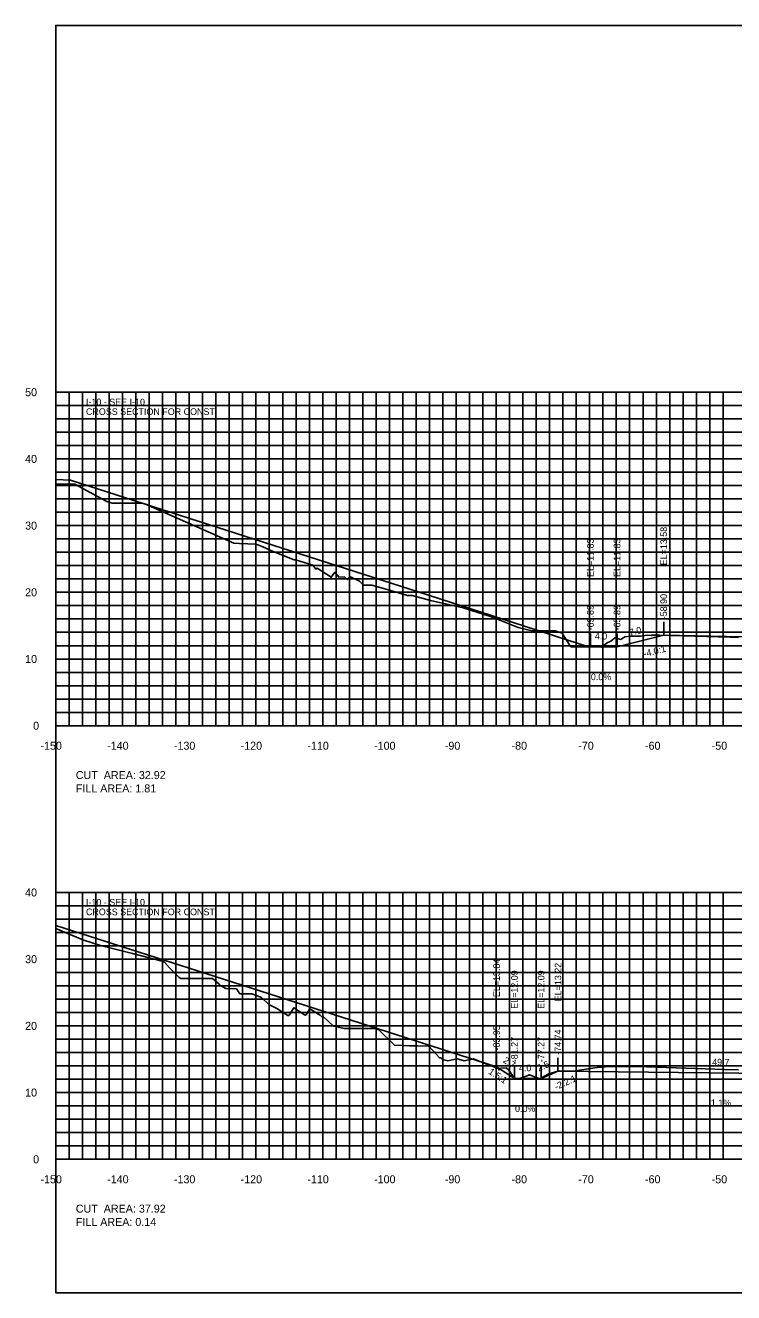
# Model space of a CAD drawing. Extents: x 1797652 to 1804145, y 245981 to 250269.
# Drawn here: x 1802136.4 to 1802242.6, y 250079.4 to 250269.4 of the extents above; entities that cross this region are included whole.
import ezdxf

# ---------------------------------------------------------------- set-up
doc = ezdxf.new("R2010")
doc.units = 0
for name, color, linetype in [('10', 7, 'Continuous'), ('3', 7, 'Continuous'), ('31', 7, 'Continuous'), ('4', 7, 'Continuous'), ('60', 7, 'Continuous'), ('ANNO-TXT', 7, 'Continuous'), ('CL-CNST', 7, 'Continuous'), ('Level 62', 7, 'Continuous'), ('M-ROADS', 7, 'Continuous')]:
    doc.layers.add(name, color=color, linetype=linetype)

msp = doc.modelspace()

# ---------------------------------------------------------------- linework, layer by layer
for p, q in [((1802232.1, 250178.01), (1802232.1, 250180.01)), ((1802221.11, 250176.26), (1802221.11, 250178.26)), ((1802225.11, 250176.26), (1802225.11, 250178.26)), ((1802207.05, 250113.27), (1802207.05, 250115.27)), ((1802216.26, 250112.65), (1802216.26, 250114.65)), ((1802209.73, 250111.52), (1802209.73, 250113.52)), ((1802213.73, 250111.52), (1802213.73, 250113.52))]:
    msp.add_line(p, q)
msp.add_lwpolyline([(1802141, 250079.43), (1802441, 250079.43), (1802441, 250269.43), (1802141, 250269.43)], close=True)
at = {"layer": '60'}
for p, q in [((1802140.94, 250214.43), (1802141, 250214.43)), ((1802141, 250164.43), (1802141, 250214.43)), ((1802140.94, 250204.43), (1802141, 250204.43)), ((1802140.94, 250194.43), (1802141, 250194.43)), ((1802140.94, 250184.43), (1802141, 250184.43)), ((1802140.94, 250174.43), (1802141, 250174.43)), ((1802140.94, 250164.43), (1802141, 250164.43)), ((1802141, 250164.43), (1802441, 250164.43)), ((1802141, 250164.37), (1802141, 250164.43)), ((1802151, 250164.37), (1802151, 250164.43)), ((1802161, 250164.37), (1802161, 250164.43)), ((1802171, 250164.37), (1802171, 250164.43)), ((1802181, 250164.37), (1802181, 250164.43)), ((1802191, 250164.37), (1802191, 250164.43)), ((1802201, 250164.37), (1802201, 250164.43)), ((1802211, 250164.37), (1802211, 250164.43)), ((1802221, 250164.37), (1802221, 250164.43)), ((1802231, 250164.37), (1802231, 250164.43)), ((1802241, 250164.37), (1802241, 250164.43)), ((1802140.94, 250139.43), (1802141, 250139.43)), ((1802141, 250099.43), (1802141, 250139.43)), ((1802140.94, 250129.43), (1802141, 250129.43)), ((1802140.94, 250119.43), (1802141, 250119.43)), ((1802140.94, 250109.43), (1802141, 250109.43)), ((1802140.94, 250099.43), (1802141, 250099.43)), ((1802141, 250099.43), (1802441, 250099.43)), ((1802141, 250099.37), (1802141, 250099.43)), ((1802151, 250099.37), (1802151, 250099.43)), ((1802161, 250099.37), (1802161, 250099.43)), ((1802171, 250099.37), (1802171, 250099.43)), ((1802181, 250099.37), (1802181, 250099.43)), ((1802191, 250099.37), (1802191, 250099.43)), ((1802201, 250099.37), (1802201, 250099.43)), ((1802211, 250099.37), (1802211, 250099.43)), ((1802221, 250099.37), (1802221, 250099.43)), ((1802231, 250099.37), (1802231, 250099.43)), ((1802241, 250099.37), (1802241, 250099.43))]:
    msp.add_line(p, q, dxfattribs=at)
at = {"layer": 'CL-CNST'}
msp.add_line((1802220.79, 250176.26), (1802224.11, 250176.26), dxfattribs=at)
for points in [[(1802141, 250201.34), (1802143.21, 250201.25), (1802196.84, 250183.99), (1802220.81, 250176.25)], [(1802221.11, 250176.26), (1802225.11, 250176.26), (1802232.1, 250178.01), (1802265.01, 250177.32), (1802269.01, 250177.16), (1802269.34, 250177.16), (1802269.51, 250176.66), (1802271.51, 250176.82), (1802275, 250176.89), (1802291, 250177.24), (1802299, 250177.3), (1802301, 250177.31), (1802301.5, 250177.4)], [(1802141, 250134.5), (1802163.5, 250127.27), (1802200.18, 250115.48), (1802207.05, 250113.27)], [(1802207.05, 250113.27), (1802209.73, 250111.52), (1802213.73, 250111.52), (1802216.26, 250112.65), (1802265.99, 250112.11), (1802269.99, 250111.95), (1802270.32, 250111.95), (1802270.49, 250111.45), (1802272.49, 250111.61), (1802275, 250111.66), (1802291, 250112.01), (1802299, 250112.19), (1802301.49, 250112.69)]]:
    msp.add_lwpolyline(points, dxfattribs=at)
at = {"layer": 'Level 62'}
for p, q in [((1802141, 250214.43), (1802441, 250214.43)), ((1802141, 250164.43), (1802141, 250214.43)), ((1802143, 250164.43), (1802143, 250214.43)), ((1802145, 250164.43), (1802145, 250214.43)), ((1802147, 250164.43), (1802147, 250214.43)), ((1802149, 250164.43), (1802149, 250214.43)), ((1802151, 250164.43), (1802151, 250214.43)), ((1802153, 250164.43), (1802153, 250214.43)), ((1802155, 250164.43), (1802155, 250214.43)), ((1802157, 250164.43), (1802157, 250214.43)), ((1802159, 250164.43), (1802159, 250214.43)), ((1802161, 250164.43), (1802161, 250214.43)), ((1802163, 250164.43), (1802163, 250214.43)), ((1802165, 250164.43), (1802165, 250214.43)), ((1802167, 250164.43), (1802167, 250214.43)), ((1802169, 250164.43), (1802169, 250214.43)), ((1802171, 250164.43), (1802171, 250214.43)), ((1802173, 250164.43), (1802173, 250214.43)), ((1802175, 250164.43), (1802175, 250214.43)), ((1802177, 250164.43), (1802177, 250214.43)), ((1802179, 250164.43), (1802179, 250214.43)), ((1802181, 250164.43), (1802181, 250214.43)), ((1802183, 250164.43), (1802183, 250214.43)), ((1802185, 250164.43), (1802185, 250214.43)), ((1802187, 250164.43), (1802187, 250214.43)), ((1802189, 250164.43), (1802189, 250214.43)), ((1802191, 250164.43), (1802191, 250214.43)), ((1802193, 250164.43), (1802193, 250214.43)), ((1802195, 250164.43), (1802195, 250214.43)), ((1802197, 250164.43), (1802197, 250214.43)), ((1802199, 250164.43), (1802199, 250214.43)), ((1802201, 250164.43), (1802201, 250214.43)), ((1802203, 250164.43), (1802203, 250214.43)), ((1802205, 250164.43), (1802205, 250214.43)), ((1802207, 250164.43), (1802207, 250214.43)), ((1802209, 250164.43), (1802209, 250214.43)), ((1802211, 250164.43), (1802211, 250214.43)), ((1802213, 250164.43), (1802213, 250214.43)), ((1802215, 250164.43), (1802215, 250214.43)), ((1802217, 250164.43), (1802217, 250214.43)), ((1802219, 250164.43), (1802219, 250214.43)), ((1802221, 250164.43), (1802221, 250214.43)), ((1802223, 250164.43), (1802223, 250214.43)), ((1802225, 250164.43), (1802225, 250214.43)), ((1802227, 250164.43), (1802227, 250214.43)), ((1802229, 250164.43), (1802229, 250214.43)), ((1802231, 250164.43), (1802231, 250214.43)), ((1802233, 250164.43), (1802233, 250214.43)), ((1802235, 250164.43), (1802235, 250214.43)), ((1802237, 250164.43), (1802237, 250214.43)), ((1802239, 250164.43), (1802239, 250214.43)), ((1802241, 250164.43), (1802241, 250214.43)), ((1802141, 250212.43), (1802441, 250212.43)), ((1802141, 250210.43), (1802441, 250210.43)), ((1802141, 250208.43), (1802441, 250208.43)), ((1802141, 250206.43), (1802441, 250206.43)), ((1802141, 250204.43), (1802441, 250204.43)), ((1802141, 250202.43), (1802441, 250202.43)), ((1802141, 250200.43), (1802441, 250200.43)), ((1802141, 250198.43), (1802441, 250198.43)), ((1802141, 250196.43), (1802441, 250196.43)), ((1802141, 250194.43), (1802441, 250194.43)), ((1802141, 250192.43), (1802441, 250192.43)), ((1802141, 250190.43), (1802441, 250190.43)), ((1802141, 250188.43), (1802441, 250188.43)), ((1802141, 250186.43), (1802441, 250186.43)), ((1802141, 250184.43), (1802441, 250184.43)), ((1802141, 250182.43), (1802441, 250182.43)), ((1802141, 250180.43), (1802441, 250180.43)), ((1802141, 250178.43), (1802441, 250178.43)), ((1802141, 250176.43), (1802441, 250176.43)), ((1802141, 250174.43), (1802441, 250174.43)), ((1802141, 250172.43), (1802441, 250172.43)), ((1802141, 250170.43), (1802441, 250170.43)), ((1802141, 250168.43), (1802441, 250168.43)), ((1802141, 250166.43), (1802441, 250166.43)), ((1802141, 250164.43), (1802441, 250164.43)), ((1802141, 250139.43), (1802441, 250139.43)), ((1802141, 250099.43), (1802141, 250139.43)), ((1802143, 250099.43), (1802143, 250139.43)), ((1802145, 250099.43), (1802145, 250139.43)), ((1802147, 250099.43), (1802147, 250139.43)), ((1802149, 250099.43), (1802149, 250139.43)), ((1802151, 250099.43), (1802151, 250139.43)), ((1802153, 250099.43), (1802153, 250139.43)), ((1802155, 250099.43), (1802155, 250139.43)), ((1802157, 250099.43), (1802157, 250139.43)), ((1802159, 250099.43), (1802159, 250139.43)), ((1802161, 250099.43), (1802161, 250139.43)), ((1802163, 250099.43), (1802163, 250139.43)), ((1802165, 250099.43), (1802165, 250139.43)), ((1802167, 250099.43), (1802167, 250139.43)), ((1802169, 250099.43), (1802169, 250139.43)), ((1802171, 250099.43), (1802171, 250139.43)), ((1802173, 250099.43), (1802173, 250139.43)), ((1802175, 250099.43), (1802175, 250139.43)), ((1802177, 250099.43), (1802177, 250139.43)), ((1802179, 250099.43), (1802179, 250139.43)), ((1802181, 250099.43), (1802181, 250139.43)), ((1802183, 250099.43), (1802183, 250139.43)), ((1802185, 250099.43), (1802185, 250139.43)), ((1802187, 250099.43), (1802187, 250139.43)), ((1802189, 250099.43), (1802189, 250139.43)), ((1802191, 250099.43), (1802191, 250139.43)), ((1802193, 250099.43), (1802193, 250139.43)), ((1802195, 250099.43), (1802195, 250139.43)), ((1802197, 250099.43), (1802197, 250139.43)), ((1802199, 250099.43), (1802199, 250139.43)), ((1802201, 250099.43), (1802201, 250139.43)), ((1802203, 250099.43), (1802203, 250139.43)), ((1802205, 250099.43), (1802205, 250139.43)), ((1802207, 250099.43), (1802207, 250139.43)), ((1802209, 250099.43), (1802209, 250139.43)), ((1802211, 250099.43), (1802211, 250139.43)), ((1802213, 250099.43), (1802213, 250139.43)), ((1802215, 250099.43), (1802215, 250139.43)), ((1802217, 250099.43), (1802217, 250139.43)), ((1802219, 250099.43), (1802219, 250139.43)), ((1802221, 250099.43), (1802221, 250139.43)), ((1802223, 250099.43), (1802223, 250139.43)), ((1802225, 250099.43), (1802225, 250139.43)), ((1802227, 250099.43), (1802227, 250139.43)), ((1802229, 250099.43), (1802229, 250139.43)), ((1802231, 250099.43), (1802231, 250139.43)), ((1802233, 250099.43), (1802233, 250139.43)), ((1802235, 250099.43), (1802235, 250139.43)), ((1802237, 250099.43), (1802237, 250139.43)), ((1802239, 250099.43), (1802239, 250139.43)), ((1802241, 250099.43), (1802241, 250139.43)), ((1802141, 250137.43), (1802441, 250137.43)), ((1802141, 250135.43), (1802441, 250135.43)), ((1802141, 250133.43), (1802441, 250133.43)), ((1802141, 250131.43), (1802441, 250131.43)), ((1802141, 250129.43), (1802441, 250129.43)), ((1802141, 250127.43), (1802441, 250127.43)), ((1802141, 250125.43), (1802441, 250125.43)), ((1802141, 250123.43), (1802441, 250123.43)), ((1802141, 250121.43), (1802441, 250121.43)), ((1802141, 250119.43), (1802441, 250119.43)), ((1802141, 250117.43), (1802441, 250117.43)), ((1802141, 250115.43), (1802441, 250115.43)), ((1802141, 250113.43), (1802441, 250113.43)), ((1802141, 250111.43), (1802441, 250111.43)), ((1802141, 250109.43), (1802441, 250109.43)), ((1802141, 250107.43), (1802441, 250107.43)), ((1802141, 250105.43), (1802441, 250105.43)), ((1802141, 250103.43), (1802441, 250103.43)), ((1802141, 250101.43), (1802441, 250101.43)), ((1802141, 250099.43), (1802441, 250099.43))]:
    msp.add_line(p, q, dxfattribs=at)
at = {"layer": 'M-ROADS'}
for points in [[(1802141, 250200.66), (1802141.59, 250200.66), (1802143.86, 250200.66), (1802148.66, 250198.03), (1802149.47, 250197.8), (1802151.76, 250197.8), (1802153.92, 250197.8), (1802154.62, 250197.58), (1802154.89, 250197.47), (1802167.68, 250191.79), (1802168.54, 250191.74), (1802171.03, 250191.67), (1802171.8, 250191.34), (1802172.01, 250191.26), (1802173.31, 250190.64), (1802176.74, 250189.28), (1802176.94, 250189.28), (1802179.51, 250188.52), (1802179.98, 250187.9), (1802180.15, 250188.05), (1802182.28, 250186.68), (1802182.84, 250187.43), (1802183.41, 250186.68), (1802184.25, 250186.75), (1802184.67, 250186.33), (1802185.16, 250186.74), (1802186.51, 250186.08), (1802187.09, 250185.5), (1802188.34, 250185.5), (1802190.33, 250184.93), (1802193.71, 250183.96), (1802194.07, 250183.96), (1802194.42, 250183.96), (1802197.15, 250183.18), (1802202.04, 250182.09), (1802206.28, 250180.73), (1802210.27, 250179.16), (1802211.3, 250178.91), (1802212.37, 250178.64), (1802214.16, 250178.64), (1802215.85, 250178.64), (1802216.88, 250178.32), (1802218.11, 250176.31), (1802218.3, 250176.26), (1802220.49, 250176.26), (1802220.64, 250176.25), (1802220.8, 250176.25), (1802222, 250176.28), (1802222.03, 250176.26), (1802222.8, 250176.23), (1802223.63, 250176.86), (1802224.18, 250177.11), (1802224.8, 250177.61), (1802225.66, 250177.37), (1802226.27, 250177.76), (1802227.13, 250177.85), (1802228.64, 250177.85), (1802229.31, 250177.96), (1802229.72, 250178.02), (1802230.24, 250177.96), (1802230.34, 250178.02), (1802231.46, 250178.03), (1802242, 250177.69), (1802243.29, 250177.69)], [(1802141, 250134.05), (1802145.04, 250132.31), (1802147.87, 250131.42), (1802147.88, 250131.42), (1802147.88, 250131.42), (1802152.48, 250130.26), (1802156.94, 250129.14), (1802157.16, 250129.04), (1802157.31, 250128.99), (1802158.02, 250128.13), (1802159.49, 250126.67), (1802159.75, 250126.53), (1802161.99, 250126.54), (1802163.95, 250126.54), (1802164.49, 250126.54), (1802165.42, 250125.74), (1802165.56, 250125.51), (1802166.46, 250125.05), (1802168.06, 250125), (1802168.59, 250124.21), (1802170.4, 250124.21), (1802170.93, 250124.01), (1802171.83, 250123.67), (1802172.94, 250122.64), (1802174.11, 250122.02), (1802175.79, 250120.99), (1802175.95, 250120.99), (1802175.98, 250121.04), (1802176.69, 250122.14), (1802178.26, 250121.08), (1802178.46, 250121.01), (1802179.08, 250121.98), (1802180.64, 250121.03), (1802180.85, 250120.8), (1802181.11, 250120.8), (1802182.59, 250119.45), (1802182.65, 250119.4), (1802182.67, 250119.38), (1802182.91, 250119.33), (1802184.22, 250119.03), (1802184.29, 250119.03), (1802186.68, 250119.04), (1802186.77, 250119.02), (1802189.05, 250119.02), (1802189.25, 250118.91), (1802189.35, 250118.9), (1802191.74, 250116.53), (1802193.99, 250116.43), (1802194.58, 250116.42), (1802194.68, 250116.43), (1802195.25, 250116.42), (1802196.81, 250116.4), (1802196.91, 250116.41), (1802198.48, 250114.64), (1802198.63, 250114.64), (1802199.13, 250114.34), (1802199.77, 250114.19), (1802200.63, 250114.39), (1802201.08, 250114.5), (1802201.21, 250114.5), (1802201.35, 250114.42), (1802202.19, 250114.17), (1802203.58, 250114.5), (1802203.59, 250114.5), (1802204.71, 250114.05), (1802207.12, 250113.08), (1802207.32, 250113.08), (1802207.41, 250112.8), (1802207.68, 250113.09), (1802208.47, 250113.12), (1802208.87, 250112.78), (1802209.73, 250111.52), (1802210.37, 250111.48), (1802211.89, 250112.04), (1802211.93, 250112.12), (1802211.98, 250112.07), (1802211.99, 250112.05), (1802212.14, 250112.05), (1802213.51, 250111.51), (1802214.88, 250112.24), (1802216.26, 250112.65), (1802218.81, 250112.71), (1802222.12, 250113.21), (1802224.04, 250113.35), (1802225.73, 250113.35), (1802227.33, 250113.35), (1802229.57, 250113.29), (1802231.09, 250113.25), (1802241.21, 250112.87), (1802243.32, 250112.85)]]:
    msp.add_lwpolyline(points, dxfattribs=at)

# ---------------------------------------------------------------- texts
for s, rotation, p in [('-4.0:1', 14.0362, (1802229.21, 250174.71)), ('1.5:1', 326.8861, (1802205.75, 250112.33)), ('-2.2:1', 24.0082, (1802216.01, 250109.8))]:
    msp.add_text(s, height=1, rotation=rotation).set_placement(p)
at = {"layer": '10'}
for s, p in [('-150', (1802138.7, 250160.83)), ('-140', (1802148.7, 250160.83)), ('-130', (1802158.7, 250160.83)), ('-120', (1802168.7, 250160.83)), ('-110', (1802178.7, 250160.83)), ('-100', (1802188.7, 250160.83)), ('-90', (1802199.3, 250160.83)), ('-80', (1802209.3, 250160.83)), ('-70', (1802219.3, 250160.83)), ('-60', (1802229.3, 250160.83)), ('-50', (1802239.3, 250160.83)), ('-150', (1802138.7, 250095.83)), ('-140', (1802148.7, 250095.83)), ('-130', (1802158.7, 250095.83)), ('-120', (1802168.7, 250095.83)), ('-110', (1802178.7, 250095.83)), ('-100', (1802188.7, 250095.83)), ('-90', (1802199.3, 250095.83)), ('-80', (1802209.3, 250095.83)), ('-70', (1802219.3, 250095.83)), ('-60', (1802229.3, 250095.83)), ('-50', (1802239.3, 250095.83))]:
    msp.add_text(s, height=1.2, dxfattribs=at).set_placement(p)
at = {"layer": '3'}
for s, p in [('I-10 - SEE I-10', (1802145.52, 250212.46)), ('CROSS SECTION FOR CONST ', (1802145.52, 250211.02)), ('CROSS SECTION FOR CONST ', (1802145.52, 250136.02)), ('I-10 - SEE I-10', (1802145.52, 250137.46))]:
    msp.add_text(s, height=1, dxfattribs=at).set_placement(p)
for s, p in [('EL=13.58', (1802232.6, 250188.48)), ('EL=11.83', (1802221.61, 250186.73)), ('EL=11.83', (1802225.61, 250186.73)), ('-58.90', (1802232.6, 250180.39)), ('-69.89', (1802221.61, 250178.72)), ('-65.89', (1802225.61, 250178.72)), ('EL=13.84', (1802207.55, 250123.74)), ('EL=12.09', (1802210.23, 250121.99)), ('EL=12.09', (1802214.23, 250121.99)), ('EL=13.22', (1802216.76, 250123.12)), ('-83.95', (1802207.55, 250115.73)), ('-74.74', (1802216.76, 250115.1)), ('-81.27', (1802210.23, 250113.98)), ('-77.27', (1802214.23, 250113.98))]:
    msp.add_text(s, height=1, rotation=90, dxfattribs=at).set_placement(p)
at = {"layer": '31'}
for s, p in [('50', (1802136.4, 250213.83)), ('40', (1802136.4, 250203.83)), ('30', (1802136.4, 250193.83)), ('20', (1802136.4, 250183.83)), ('10', (1802136.4, 250173.83)), ('0', (1802137.6, 250163.83)), ('40', (1802136.4, 250138.83)), ('30', (1802136.4, 250128.83)), ('20', (1802136.4, 250118.83)), ('10', (1802136.4, 250108.83)), ('0', (1802137.6, 250098.83))]:
    msp.add_text(s, height=1.2, dxfattribs=at).set_placement(p)
at = {"layer": '4'}
for s, rotation, p in [('7.0', 14.0362, (1802227.06, 250177.88)), ('2.7', 326.8861, (1802207.92, 250114.02)), ('2.5', 24.0082, (1802213.38, 250112.57)), ('49.7', 359.376, (1802239.36, 250113.5)), ('1.1%', 359.376, (1802239.16, 250107.4))]:
    msp.add_text(s, height=1, rotation=rotation, dxfattribs=at).set_placement(p)
for s, p in [('4.0', (1802221.78, 250177.36)), ('0.0%', (1802221.19, 250171.26)), ('4.0', (1802210.41, 250112.62)), ('0.0%', (1802209.82, 250106.52))]:
    msp.add_text(s, height=1, dxfattribs=at).set_placement(p)
at = {"layer": '60'}
for p in [(1802141, 250164.43), (1802141, 250099.43)]:
    msp.add_text('-', height=0.0001, dxfattribs=at).set_placement(p)
at = {"layer": 'ANNO-TXT'}
for s, p in [('CUT  AREA: 32.92', (1802144, 250156.43)), ('FILL AREA: 1.81', (1802144, 250154.43)), ('CUT  AREA: 37.92', (1802144, 250091.43)), ('FILL AREA: 0.14', (1802144, 250089.43))]:
    msp.add_text(s, height=1.2, dxfattribs=at).set_placement(p)

doc.saveas('drawing.dxf')
